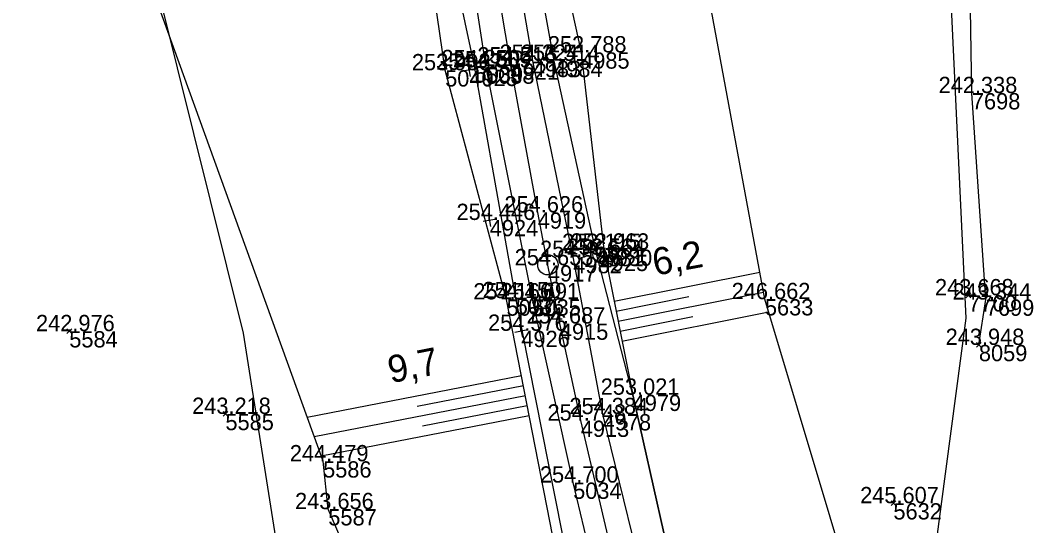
# Model space of a CAD drawing. Extents: x -809970 to -809480, y -1011362 to -1010672.
# Drawn here: x -809887.1 to -809812.8, y -1010969.8 to -1010932.6 of the extents above; entities that cross this region are included whole.
import ezdxf

# ---------------------------------------------------------------- set-up
doc = ezdxf.new("R2010")
doc.units = 0
for name, color, linetype in [('Vrstva 1', 7, 'Continuous'), ('Vrstva 17', 7, 'Continuous'), ('Vrstva 4', 7, 'Continuous'), ('Vrstva 48', 7, 'Continuous'), ('Vrstva 49', 7, 'Continuous'), ('Vrstva 53', 7, 'Continuous'), ('Vrstva 60', 7, 'Continuous'), ('Vrstva 61', 7, 'Continuous'), ('Vrstva 7', 7, 'Continuous')]:
    doc.layers.add(name, color=color, linetype=linetype)

msp = doc.modelspace()

# ---------------------------------------------------------------- linework, layer by layer
at = {"layer": 'Vrstva 1'}
msp.add_lwpolyline([(-809820.002, -1011038.37), (-809825.442, -1011026.104), (-809830.785, -1011012.658), (-809834.485, -1011002.308), (-809836.415, -1010996.462), (-809838.541, -1010989.632), (-809841.189, -1010980.417), (-809842.723, -1010974.633), (-809843.612, -1010971.08), (-809845.723, -1010962.088), (-809847.264, -1010954.929), (-809848.141, -1010950.637), (-809848.896, -1010946.737), (-809850.898, -1010935.751), (-809852.809, -1010924.513), (-809856.326, -1010902.237), (-809858.786, -1010885.982), (-809860.306, -1010875.864), (-809863.238, -1010856.222), (-809865.824, -1010838.832), (-809869.271, -1010815.693)], dxfattribs=at)
at = {"layer": 'Vrstva 17'}
msp.add_lwpolyline([(-809816.368, -1010956.508), (-809815.855, -1010953.161), (-809816.885, -1010937.943), (-809817.019, -1010930.187), (-809812.79, -1010929.244), (-809814.558, -1010888.198), (-809811.641, -1010871.97), (-809791.356, -1010869.614)], dxfattribs=at)
at = {"layer": 'Vrstva 4'}
for points in [[(-809821.494, -1011039.157), (-809826.205, -1011028.819), (-809833.001, -1011011.481), (-809837.78, -1010997.54), (-809838.806, -1010997.207), (-809843.283, -1010980.934), (-809843.041, -1010980.213), (-809846.285, -1010966.658), (-809849.289, -1010953.139), (-809852.706, -1010936.051), (-809854.789, -1010922.512), (-809857.871, -1010903.005), (-809861.561, -1010877.867), (-809862.279, -1010876.008), (-809867.764, -1010839.12), (-809867.776, -1010837.677), (-809868.98, -1010830.232), (-809873.561, -1010797.792), (-809876.118, -1010779.988), (-809878.6, -1010761.673), (-809881.093, -1010740.742), (-809883.606, -1010712.064)], [(-809818.366, -1011037.45), (-809824.503, -1011023.859), (-809827.98, -1011014.861), (-809832.548, -1011002.245), (-809834.342, -1010996.578), (-809834.105, -1010995.845), (-809838.678, -1010979.669), (-809839.533, -1010979.34), (-809840.375, -1010976.742), (-809844.107, -1010961.611), (-809846.272, -1010950.024), (-809849.263, -1010935.563), (-809851.188, -1010924.288), (-809854.685, -1010902.149), (-809857.441, -1010883.897), (-809858.703, -1010875.93), (-809858.211, -1010875.546), (-809863.759, -1010838.589), (-809864.243, -1010838.113), (-809864.684, -1010833.803), (-809870.275, -1010797.222)], [(-809838.678, -1010979.669), (-809838.423, -1010979.516), (-809837.883, -1010979.54), (-809837.013, -1010979.451), (-809837.103, -1010978.997), (-809837.176, -1010978.22), (-809837.88, -1010976.841), (-809838.297, -1010976.333), (-809838.847, -1010973.75), (-809841.894, -1010960.179), (-809844.644, -1010949.504), (-809847.686, -1010935.566), (-809849.835, -1010923.843), (-809853.415, -1010901.801), (-809856.171, -1010883.326), (-809856.72, -1010879.277), (-809857.134, -1010878.975), (-809857.359, -1010879.02), (-809857.838, -1010876.123), (-809858.079, -1010875.541), (-809858.211, -1010875.546)], [(-809843.283, -1010980.934), (-809843.235, -1010980.877), (-809844.412, -1010980.573), (-809845.115, -1010978.271), (-809845.085, -1010978.25), (-809845.209, -1010978.233), (-809846.601, -1010972.791), (-809850.517, -1010953.058), (-809853.547, -1010935.954), (-809856.396, -1010922.703), (-809859.23, -1010902.96), (-809862.455, -1010881.274), (-809862.589, -1010879.865), (-809862.252, -1010879.786), (-809862, -1010879.706), (-809862.476, -1010876.825), (-809862.419, -1010876.062), (-809862.279, -1010876.008)]]:
    msp.add_lwpolyline(points, dxfattribs=at)
at = {"layer": 'Vrstva 48'}
for p, q in [((-809843.27, -1010953.277), (-809832.516, -1010951.133)), ((-809842.977, -1010954.748), (-809832.243, -1010952.608)), ((-809843.123, -1010954.012), (-809837.751, -1010952.941)), ((-809842.684, -1010956.219), (-809831.868, -1010954.062)), ((-809842.83, -1010955.483), (-809837.457, -1010954.412)), ((-809850.095, -1010958.784), (-809865.885, -1010961.864)), ((-809849.951, -1010959.521), (-809857.789, -1010961.049)), ((-809849.808, -1010960.257), (-809865.369, -1010963.292)), ((-809849.664, -1010960.993), (-809857.387, -1010962.499)), ((-809849.52, -1010961.729), (-809864.853, -1010964.72))]:
    msp.add_line(p, q, dxfattribs=at)
at = {"layer": 'Vrstva 49'}
for p, q in [((-809817.326, -1010952.672), (-809816.972, -1010953.026)), ((-809817.326, -1010953.026), (-809816.972, -1010952.672)), ((-809883.612, -1010955.317), (-809883.258, -1010955.671)), ((-809883.612, -1010955.671), (-809883.258, -1010955.317)), ((-809816.545, -1010956.331), (-809816.191, -1010956.685)), ((-809816.545, -1010956.685), (-809816.191, -1010956.331)), ((-809872.1, -1010961.416), (-809871.746, -1010961.77)), ((-809872.1, -1010961.77), (-809871.746, -1010961.416)), ((-809822.848, -1010968), (-809822.494, -1010968.354)), ((-809822.848, -1010968.354), (-809822.494, -1010968))]:
    msp.add_line(p, q, dxfattribs=at)
for points in [[(-809856.883, -1010875.823), (-809855.422, -1010883.15), (-809852.222, -1010901.25), (-809848.214, -1010923.392), (-809845.696, -1010934.941), (-809844.027, -1010949.48), (-809841.894, -1010960.179), (-809838.847, -1010973.75), (-809838.297, -1010976.333), (-809838.163, -1010976.258), (-809836.936, -1010979.029), (-809837.013, -1010979.451), (-809825.985, -1010977.935), (-809824.923, -1010977.248)], [(-809824.923, -1010977.248), (-809832.146, -1010953.133), (-809837.944, -1010921.765), (-809839.29, -1010906.656), (-809832.688, -1010885.218), (-809835.079, -1010880.738), (-809839.978, -1010876.967), (-809844.518, -1010876.01), (-809844.618, -1010877), (-809856.883, -1010875.823)], [(-809844.216, -1010981.17), (-809845.209, -1010978.233), (-809845.714, -1010977.964), (-809847.365, -1010972.779), (-809851.193, -1010953.154), (-809855.722, -1010936.261), (-809857.298, -1010925.409), (-809860.607, -1010903.381), (-809863.59, -1010882.451), (-809864.222, -1010876.871), (-809865.405, -1010877.268)], [(-809846.733, -1010986.717), (-809852.633, -1010985.242), (-809855.833, -1010983.597), (-809858.12, -1010981.877), (-809860.248, -1010978.081), (-809864.337, -1010968.616), (-809864.72, -1010965.088), (-809878.39, -1010927.249), (-809884.518, -1010905.485), (-809883.3, -1010886.554), (-809883.077, -1010886.562), (-809880.73, -1010884.265), (-809876.323, -1010881.843), (-809865.405, -1010877.268)]]:
    msp.add_lwpolyline(points, dxfattribs=at)
at = {"layer": 'Vrstva 53'}
for points in [[(-809810.89, -1011076.81), (-809836.26, -1011028.53), (-809850.32, -1011003.33), (-809854.51, -1011000.24), (-809856.34, -1010998.68), (-809859.52, -1010995.97), (-809864.77, -1010992.44), (-809865.72, -1010986.44), (-809870.58, -1010955.65), (-809883.99, -1010901.78), (-809890.33, -1010872.36), (-809892.39, -1010868.68), (-809893.92, -1010865.41), (-809894.78, -1010861.65), (-809898.21, -1010828.41), (-809898.47, -1010814.6), (-809887.66, -1010796.86), (-809893.8, -1010725.05), (-809890.92, -1010677.02)], [(-809848.47, -1010824.63), (-809848.99, -1010834.52), (-809828.94, -1010831.94), (-809811.76, -1010846.11), (-809806.99, -1010849.89), (-809798.33, -1010856.76), (-809803.49, -1010861.61), (-809820.27, -1010877.38), (-809819.54, -1010907.65), (-809817.34, -1010954.54), (-809819.55, -1010971.19), (-809826.87, -1010981.55), (-809825.08, -1010988.69), (-809823.59, -1010994.66), (-809817.83, -1011024.91), (-809805.06, -1011048.21)]]:
    msp.add_lwpolyline(points, dxfattribs=at)
at = {"layer": 'Vrstva 60'}
for p, q in [((-809845.696, -1010934.941), (-809845.696, -1010934.941)), ((-809850.898, -1010935.751), (-809850.898, -1010935.751)), ((-809849.263, -1010935.563), (-809849.263, -1010935.563)), ((-809847.686, -1010935.566), (-809847.686, -1010935.566)), ((-809855.722, -1010936.261), (-809855.722, -1010936.261)), ((-809853.931, -1010936.222), (-809853.931, -1010936.222)), ((-809853.547, -1010935.954), (-809853.547, -1010935.954)), ((-809852.706, -1010936.051), (-809852.706, -1010936.051)), ((-809816.885, -1010937.943), (-809816.885, -1010937.943)), ((-809848.896, -1010946.737), (-809848.896, -1010946.737)), ((-809852.433, -1010947.296), (-809852.433, -1010947.296)), ((-809844.644, -1010949.504), (-809844.644, -1010949.504)), ((-809844.327, -1010949.862), (-809844.327, -1010949.862)), ((-809844.027, -1010949.48), (-809844.027, -1010949.48)), ((-809848.141, -1010950.637), (-809848.141, -1010950.637)), ((-809846.272, -1010950.024), (-809846.272, -1010950.024)), ((-809817.149, -1010952.849), (-809817.149, -1010952.849)), ((-809851.193, -1010953.154), (-809851.193, -1010953.154)), ((-809850.517, -1010953.058), (-809850.517, -1010953.058)), ((-809849.289, -1010953.139), (-809849.289, -1010953.139)), ((-809832.146, -1010953.133), (-809832.146, -1010953.133)), ((-809815.855, -1010953.161), (-809815.855, -1010953.161)), ((-809847.264, -1010954.929), (-809847.264, -1010954.929)), ((-809883.435, -1010955.494), (-809883.435, -1010955.494)), ((-809850.106, -1010955.466), (-809850.106, -1010955.466)), ((-809816.368, -1010956.508), (-809816.368, -1010956.508)), ((-809841.894, -1010960.179), (-809841.894, -1010960.179)), ((-809871.923, -1010961.593), (-809871.923, -1010961.593)), ((-809844.107, -1010961.611), (-809844.107, -1010961.611)), ((-809845.723, -1010962.088), (-809845.723, -1010962.088)), ((-809864.72, -1010965.088), (-809864.72, -1010965.088)), ((-809846.285, -1010966.658), (-809846.285, -1010966.658)), ((-809822.671, -1010968.177), (-809822.671, -1010968.177)), ((-809864.337, -1010968.616), (-809864.337, -1010968.616))]:
    msp.add_line(p, q, dxfattribs=at)
at = {"layer": 'Vrstva 7'}
for p, q in [((-809853.847, -1010936.715), (-809854.015, -1010935.729)), ((-809854.424, -1010936.306), (-809853.438, -1010936.138)), ((-809852.343, -1010947.788), (-809852.523, -1010946.804)), ((-809852.925, -1010947.386), (-809851.941, -1010947.206)), ((-809844.317, -1010949.911), (-809844.337, -1010949.813)), ((-809850.006, -1010955.956), (-809850.206, -1010954.976)), ((-809850.596, -1010955.566), (-809849.616, -1010955.366))]:
    msp.add_line(p, q, dxfattribs=at)
for centre, radius in [((-809848.148, -1010950.602), 0.75), ((-809844.327, -1010949.862), 0.5)]:
    msp.add_circle(centre, radius, dxfattribs=at)

# ---------------------------------------------------------------- texts
at = {"layer": 'Vrstva 48'}
for s, rotation, p in [('6,2', 10.47225, (-809840.246, -1010951.412)), ('9,7', 11.03737, (-809859.737, -1010959.337))]:
    msp.add_text(s, height=2, rotation=rotation, dxfattribs=at).set_placement(p)
at = {"layer": 'Vrstva 60'}
for s, p in [('4985', (-809845.696, -1010936.141)), ('4921', (-809850.898, -1010936.951)), ('4983', (-809849.263, -1010936.763)), ('4984', (-809847.686, -1010936.766)), ('5040', (-809855.722, -1010937.461)), ('4923', (-809853.931, -1010937.422)), ('5039', (-809853.547, -1010937.154)), ('5038', (-809852.706, -1010937.251)), ('7698', (-809816.885, -1010939.143)), ('4919', (-809848.896, -1010947.937)), ('4924', (-809852.433, -1010948.496)), ('4981', (-809844.644, -1010950.704)), ('4925', (-809844.327, -1010951.062)), ('4980', (-809844.027, -1010950.68)), ('4917', (-809848.141, -1010951.837)), ('4982', (-809846.272, -1010951.224)), ('7700', (-809817.149, -1010954.049)), ('5037', (-809851.193, -1010954.354)), ('5036', (-809850.517, -1010954.258)), ('5035', (-809849.289, -1010954.339)), ('5633', (-809832.146, -1010954.333)), ('7699', (-809815.855, -1010954.361)), ('4915', (-809847.264, -1010956.129)), ('5584', (-809883.435, -1010956.694)), ('4926', (-809850.106, -1010956.666)), ('8059', (-809816.368, -1010957.708)), ('4979', (-809841.894, -1010961.379)), ('5585', (-809871.923, -1010962.793)), ('4978', (-809844.107, -1010962.811)), ('4913', (-809845.723, -1010963.288)), ('5586', (-809864.72, -1010966.288)), ('5034', (-809846.285, -1010967.858)), ('5632', (-809822.671, -1010969.377)), ('5587', (-809864.337, -1010969.816))]:
    msp.add_text(s, height=1.2, dxfattribs=at).set_placement(p)
at = {"layer": 'Vrstva 61'}
for s, p in [('252.788', (-809848.15, -1010934.941)), ('253.906', (-809858.174, -1010936.261)), ('254.374', (-809856.382, -1010936.222)), ('254.250', (-809855.998, -1010935.954)), ('254.509', (-809855.16, -1010936.051)), ('254.516', (-809853.35, -1010935.751)), ('254.224', (-809851.714, -1010935.563)), ('253.514', (-809850.137, -1010935.566)), ('242.338', (-809819.339, -1010937.943)), ('254.446', (-809854.885, -1010947.296)), ('254.626', (-809851.348, -1010946.737)), ('253.115', (-809847.1, -1010949.504)), ('252.963', (-809846.479, -1010949.48)), ('254.466', (-809848.724, -1010950.024)), ('253.564', (-809846.778, -1010949.862)), ('254.655', (-809850.597, -1010950.637)), ('254.166', (-809853.645, -1010953.154)), ('254.150', (-809852.968, -1010953.058)), ('254.691', (-809851.646, -1010953.139)), ('246.662', (-809834.594, -1010953.133)), ('243.668', (-809819.603, -1010952.849)), ('243.344', (-809818.306, -1010953.161)), ('242.976', (-809885.887, -1010955.494)), ('254.576', (-809852.558, -1010955.466)), ('254.687', (-809849.716, -1010954.929)), ('243.948', (-809818.822, -1010956.508)), ('253.021', (-809844.251, -1010960.179)), ('243.218', (-809874.377, -1010961.593)), ('254.748', (-809848.177, -1010962.088)), ('254.384', (-809846.558, -1010961.611)), ('244.479', (-809867.174, -1010965.088)), ('254.700', (-809848.736, -1010966.658)), ('245.607', (-809825.123, -1010968.177)), ('243.656', (-809866.789, -1010968.616))]:
    msp.add_text(s, height=1.2, dxfattribs=at).set_placement(p)

doc.saveas('drawing.dxf')
